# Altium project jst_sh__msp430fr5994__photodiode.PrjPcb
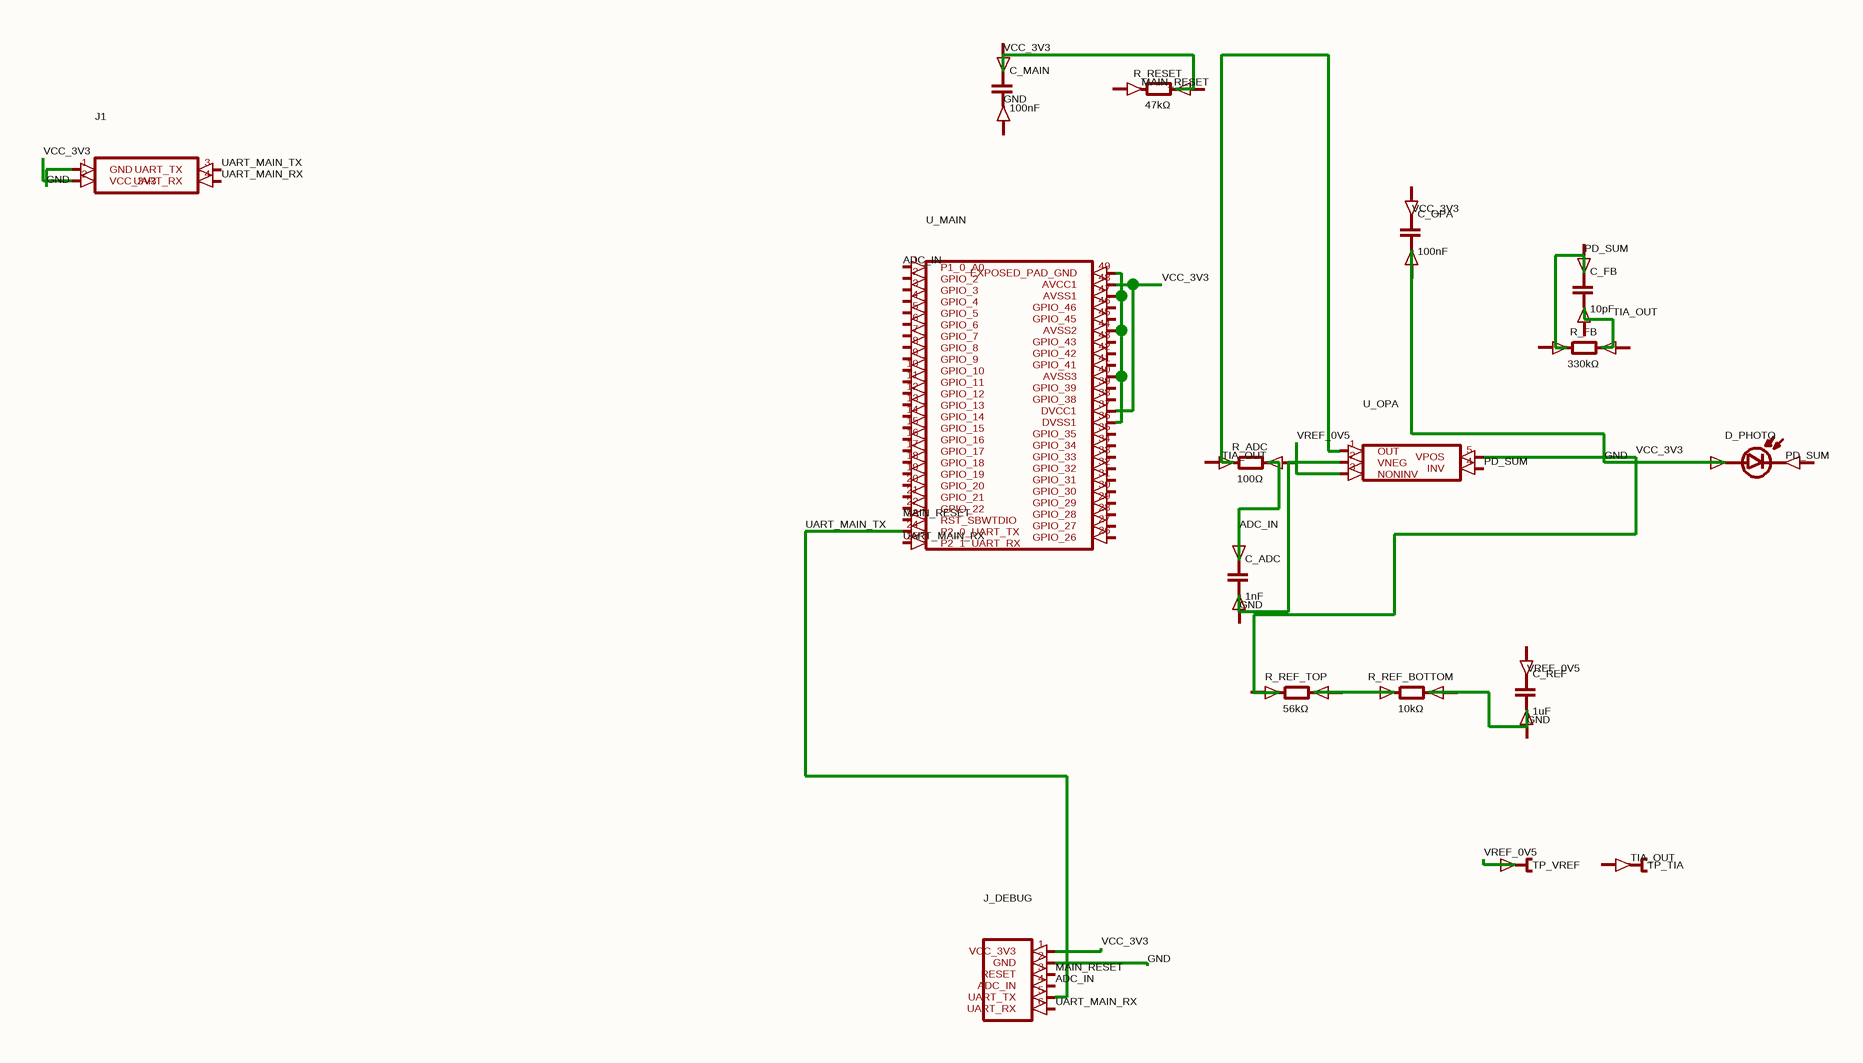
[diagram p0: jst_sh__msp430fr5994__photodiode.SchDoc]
1 sheet, 17 parts. Net scope: global (net labels, ports and power ports of the same name join across sheets).
Board file: jst_sh__msp430fr5994__photodiode.PcbDoc

## Sheet jst_sh__msp430fr5994__photodiode.SchDoc
size 207 x 135 mm

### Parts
C_ADC  1nF
C_FB  10pF
C_MAIN  100nF
C_OPA  100nF
C_REF  1uF
D_PHOTO  (no value)
J1  (no value)
J_DEBUG  (no value)
R_ADC  100Ω
R_FB  330kΩ
R_REF_BOTTOM  10kΩ
R_REF_TOP  56kΩ
R_RESET  47kΩ
TP_TIA  (no value)
TP_VREF  (no value)
U_MAIN  (no value)
U_OPA  (no value)

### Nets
ADC_IN: C_ADC.1(anode) J_DEBUG.4(ADC_IN) U_MAIN.1(P1_0_A0)
GND: C_OPA.2(cathode) D_PHOTO.1(anode) J1.1(GND) J1.2(VCC_3V3) J1.3(UART_TX) J_DEBUG.1(VCC_3V3) J_DEBUG.2(GND) J_DEBUG.5(UART_TX) R_ADC.2(cathode) R_REF_BOTTOM.2(cathode) TP_VREF.1(pin1) U_MAIN.24(P2_0_UART_TX) U_MAIN.36(DVSS1) U_MAIN.37(DVCC1) U_MAIN.40(AVSS3) U_MAIN.44(AVSS2) U_MAIN.47(AVSS1) U_MAIN.48(AVCC1) U_MAIN.49(EXPOSED_PAD_GND) U_OPA.2(VNEG) U_OPA.3(NONINV) U_OPA.5(VPOS)  [also labelled UART_MAIN_TX, VCC_3V3, VREF_0V5]
MAIN_RESET: J_DEBUG.3(RESET) U_MAIN.23(RST_SBWTDIO)
PD_SUM: U_OPA.4(INV)
TIA_OUT: U_OPA.1(OUT)
UART_MAIN_RX: J1.4(UART_RX) J_DEBUG.6(UART_RX) U_MAIN.25(P2_1_UART_RX)
NetR_REF_BOTTOM_1: R_REF_BOTTOM.1(anode) R_REF_TOP.2(cathode)

Not connected (* = marked no-connect by the designer): C_ADC 2(cathode); C_FB 1(anode) 2(cathode); C_MAIN 1(anode) 2(cathode); C_OPA 1(anode); C_REF 1(anode) 2(cathode); D_PHOTO 2(cathode); R_ADC 1(anode); R_FB 1(anode) 2(cathode); R_REF_TOP 1(anode); R_RESET 1(anode) 2(cathode); TP_TIA 1(pin1); U_MAIN 2(GPIO_2) 3(GPIO_3) 4(GPIO_4) 5(GPIO_5) 6(GPIO_6) 7(GPIO_7) 8(GPIO_8) 9(GPIO_9) 10(GPIO_10) 11(GPIO_11) 12(GPIO_12) 13(GPIO_13) 14(GPIO_14) 15(GPIO_15) 16(GPIO_16) 17(GPIO_17) 18(GPIO_18) 19(GPIO_19) 20(GPIO_20) 21(GPIO_21) 22(GPIO_22) 26(GPIO_26) 27(GPIO_27) 28(GPIO_28) 29(GPIO_29) 30(GPIO_30) 31(GPIO_31) 32(GPIO_32) 33(GPIO_33) 34(GPIO_34) 35(GPIO_35) 38(GPIO_38) 39(GPIO_39) 41(GPIO_41) 42(GPIO_42) 43(GPIO_43) 45(GPIO_45) 46(GPIO_46)

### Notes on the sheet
- Labels drawn without touching a wire or pin: GND, MAIN_RESET, PD_SUM, TIA_OUT, VCC_3V3, VREF_0V5

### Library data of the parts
C_ADC C_FB C_MAIN C_OPA C_REF = capacitor_down
D_PHOTO = photodiode_horz
J1 = J1
J_DEBUG = J_DEBUG
R_ADC R_FB R_REF_BOTTOM R_REF_TOP R_RESET = boxresistor_right
TP_TIA TP_VREF = testpoint_right
U_MAIN = U_MAIN
U_OPA = U_OPA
